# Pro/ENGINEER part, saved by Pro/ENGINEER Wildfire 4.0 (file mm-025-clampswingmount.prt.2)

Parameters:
  METRIC = "NO"

Other parameters: PITCH, DRILL_DIAMETER, THREAD_DIAMETER, THREADS_PER_INCH, CBORE_DIAMETER, CBORE_DEPTH, DRILL_POINT_ANGLE, DRILL_DEPTH, THREAD_DEPTH, THREAD_LENGTH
